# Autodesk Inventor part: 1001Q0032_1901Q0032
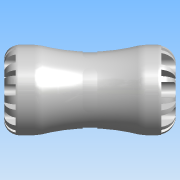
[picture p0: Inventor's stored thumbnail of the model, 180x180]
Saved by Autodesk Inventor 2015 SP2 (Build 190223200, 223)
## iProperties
Created: 2016-12
Part Number: 1001Q0032_1901Q0032
Material: PVC-Piping
Description: PLASSON PVC TO PE COUPLER 32 SERIES 1
Document SubType Name: Modeling
Designer: KIM
Mass: 95.2094 g
Surface Area: 200.83 cm^2
Volume: 68.0067 cm^3
Density: 1.4 g/cm^3
Appearance: Smooth - White
ILogicFactory: False
Author: KIM
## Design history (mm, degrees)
derived "1001Q.ipt"
feature "Solid1::1001Q.ipt"
tag "TaggingFeature1"
body "Solid1"
other parameters: "d1" = 58, "d2" = 53, "d11" = 7.2, "d13" = 7.2, "d14" = 0, "d16" = 360 deg, "d18" = 8 deg, "d19" = 0.64, "d20" = 8 deg, "d21" = 0.64, "d23" = 0, "d25" = 360 deg, "d27" = 23.2, "d28" = 9.6, "d29" = 9.6, "d30" = 14.112, "d31" = 0, "d33" = 0, "d37" = 22, "d38" = 0.58, "d44" = 32, "d45" = 22, "d47" = 58, "d50" = 360 deg, "d54" = 0.513, "d60" = 32, "d61" = 35.2, "d63" = 22, "d65" = 55, "d66" = 2.66667, "d67" = 55, "d70" = 10.26, "d72" = 9.12, "d73" = 0, "d75" = 360 deg, "d77" = 8 deg, "d78" = 8 deg, "d79" = 0.64, "d80" = 0.64, "d82" = 0, "d84" = 360 deg, "d93" = 58, "d94" = 49.3, "d_" = 32, "E_" = 58, "l_" = 53, "d_1" = 32, "l_1" = 55, "d42" = 58, "d52" = 9, "d68" = 58, "d69" = 35.2, "d71" = 11.4
